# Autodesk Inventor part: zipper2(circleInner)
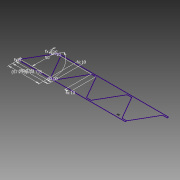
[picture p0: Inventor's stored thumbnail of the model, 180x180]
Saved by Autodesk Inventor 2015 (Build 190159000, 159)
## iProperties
Created: 2015-02
Part Number: zipper2(circleInner)
Material: Generic
Document SubType Name: Modeling
Designer: sungeun
Density: 1 g/cm^3
Appearance: Default
Author: sungeun
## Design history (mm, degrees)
sketch "Sketch1"
  geometry: L1 (0, 3)-(28.868, 53); L2 (28.868, 53)-(38.868, 53); L3 (38.868, 53)-(67.735, 3); L4 (67.735, 3)-(77.735, 3); L5 (77.735, 0)-(0, 0); L6 (28.868, 56)-(116.603, 56); L7 (116.603, 53)-(106.603, 53); L8 (106.603, 53)-(77.735, 3); L9 (77.735, 3)-(106.603, 53); L10 (106.603, 53)-(116.603, 53); L11 (116.603, 53)-(145.47, 3); L12 (145.47, 3)-(155.47, 3); L13 (155.47, 0)-(77.735, 0); L14 (106.603, 56)-(194.338, 56); L15 (194.338, 53)-(184.338, 53); L16 (184.338, 53)-(155.47, 3); L17 (155.47, 3)-(184.338, 53); L18 (184.338, 53)-(194.338, 53); L19 (194.338, 53)-(223.205, 3); L20 (223.205, 3)-(233.205, 3); L21 (233.205, 0)-(155.47, 0); L22 (184.338, 56)-(272.073, 56); L23 (272.073, 53)-(262.073, 53); L24 (262.073, 53)-(233.205, 3); L25 (272.073, 56)-(272.073, 53); L26 (233.205, 3)-(233.205, 0); L27 (28.868, 56)-(28.868, 53); L28 (0, 3)-(0, 0); L29 (210.186, 7.284)-(215.439, 7.284); L30 (215.439, 7.284)-(215.439, 3.639); L31 (215.439, 3.639)-(210.186, 3.639); L32 (210.186, 3.639)-(210.186, 7.284)
  constraints: 56 end point, 4 parallel, 2 equal length, 2 horizontal, 1 collinear, 1 perpendicular, 1 vertical, 39 other
  dimensions: "d0" = 3 distance of L5.end L1.start; "d1" = 10 distance of L1.end L2.end; "d2" = 60 deg angle of L5 L1; "d3" = 50 distance between parallel lines of L4 L2; "d4" = 3 distance between parallel lines of L5 L4 (= d0); "d14" = 3 distance of L1.end L6.start (= d4); "d17" = 3 distance between parallel lines of L6 L7 (= d0); "d18" = 10 distance of L7.start L7.end (= d1); "d28" = 77.73503 distance of L5.end L13.end (= d35 + d34); "d33" = 77.73503 distance of L1.start L9.start (derived); "d34" = 10 distance of L3.end L4.end (= d1); "d35" = 67.73503 distance of L1.start L3.end (derived)
other parameters: "d6" = 56.39702 (derived)
